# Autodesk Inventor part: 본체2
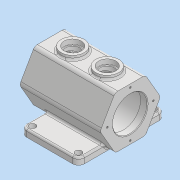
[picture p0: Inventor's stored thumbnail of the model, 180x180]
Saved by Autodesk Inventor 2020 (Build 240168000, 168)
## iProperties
Created: 2021-06
Part Number: 본체2
Material: 일반
Document SubType Name: Modeling
Designer: MIRAE
Density: 1 g/cm^3
Appearance: 기본값
Author: MIRAE
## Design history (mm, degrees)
sketch "스케치1"
  geometry: L1 (50, -75)-(-50, -75); L2 (-50, -75)-(-50, 75); L3 (-50, 75)-(50, 75); L4 (50, 75)-(50, -75); L5 (50, -75)-(-50, 75); L6 (-50, -75)-(50, 75); 1 further point
  constraints: 12 end point, 2 midpoint, 2 parallel, 1 horizontal, 1 perpendicular
  dimensions: "d0" = 100 distance of L2.end L3.end; "d1" = 150 distance of L1.end L2.end
extrude "돌출1" new body sketch "스케치1" distance "d2" = 12; taper "d3" = 0 deg
fillet "모깎기1" dims "d51" = 10
sketch "스케치8"
  geometry: C1 r 5.5 at (-40, 65); A1 r 10 centre (-40, 65) between (-40, 75) and (-50, 65) reference; 1 further point
  constraints: 1 centre point, 1 coincident
  dimensions: "d52" = 11 diameter of C1
extrude "돌출4" cut sketch "스케치8" extent not by distance; stored distance "d53" = 0; taper "d54" = 0 deg
sketch "스케치9"
  geometry: L1 (-50, 65)-(-50, -65) reference; L2 (40, 75)-(-40, 75) reference; 4 further points
  constraints: 1 vertical alignment, 1 other
  dimensions: "d65" = 50 distance from line of L1 point (0, 61) (derived); "d66" = 14 distance from line of point (0, 61) L2
feature "엠보싱1" sketch "스케치9" dims "d0" = 100, "d1" = 150, "d67" = 0.5, "d68" = 0
sketch "스케치10" dims "d72" = 105
  geometry: L1 (0, 50)-(-52.5, 50); L2 (-52.5, 50)-(-26.25, 95.466); L3 (-26.25, 95.466)-(26.25, 95.466); L4 (26.25, 95.466)-(52.5, 50); L5 (52.5, 50)-(26.25, 4.534); L6 (26.25, 4.534)-(-26.25, 4.534); L7 (-26.25, 4.534)-(-52.5, 50); L8 (-65, 0)-(65, 0) reference; 2 further points
  constraints: 14 end point, 1 coincident, 1 horizontal, 1 horizontal alignment, 15 other
  dimensions: "d73" = 50 distance between parallel lines of L8 L1
extrude "돌출5" join sketch "스케치10" distance "d74" = 75; taper "d75" = 0 deg
sketch "스케치11"
  geometry: L1 (-50, 52.5)-(-95.466, 26.25) reference; L2 (-95.466, -26.25)-(-50, -52.5) reference; L3 (-12, 30.561)-(-12, -30.561) reference; L4 (-12, 30.561)-(-50, 52.5) reference; L5 (-50, 52.5)-(-95.466, 26.25) reference; L6 (-95.466, 26.25)-(-95.466, -26.25) reference; L7 (-95.466, -26.25)-(-50, -52.5) reference; L8 (-50, -52.5)-(-12, -30.561) reference; L9 (-50, -52.5)-(-95.466, -26.25); L10 (-95.466, -26.25)-(-95.466, 26.25); L11 (-95.466, 26.25)-(-50, 52.5); L12 (-50, 52.5)-(-4.534, 26.25); L13 (-4.534, 26.25)-(-4.534, -26.25); L14 (-4.534, -26.25)-(-50, -52.5); 8 further points
  constraints: 12 end point, 13 other
extrude "돌출6" join sketch "스케치11" distance "d76" = 65; taper "d77" = 0 deg
sketch "스케치12"
  geometry: L1 (75, 50)-(-65, 50) reference; L2 (75, 50)-(-65, 50); L3 (75, 50)-(63, 50); L4 (63, 50)-(63, 80); L5 (63, 80)-(75, 80); L6 (75, 80)-(75, 50); L7 (63, 50)-(-53, 50); L8 (-53, 50)-(-53, 87.5); L9 (-53, 87.5)-(63, 87.5); L10 (63, 87.5)-(63, 50); L11 (-65, 50)-(-65, 95.466) reference; L12 (-53, 50)-(-65, 50); L13 (-65, 50)-(-65, 80); L14 (-65, 80)-(-53, 80); L15 (-53, 80)-(-53, 50); 3 further points
  constraints: 26 end point, 6 parallel, 4 horizontal, 3 perpendicular, 1 point on line
  dimensions: "d78" = 12 distance of L13.end L14.end; "d79" = 12 distance of L4.end L5.end; "d80" = 60 diameter of L5 L1; "d81" = 75 diameter of L9 L1; "d82" = 60 diameter of L14 L1
revolve "회전2" sketch "스케치12" stored, may be unused: angle "d83" = 90 deg
chamfer "모따기3" distance "d84" = 1; stored, may be unused: second distance "d85" = 2, angle "d86" = 45 deg
node "작업 평면2"
sketch "스케치13"
  geometry: L1 (-75, -26.25)-(-75, 26.25) reference; C1 r 20 at (-35, 0); C2 r 20 at (25, 0); 1 further point
  constraints: 2 centre point, 2 horizontal alignment
  dimensions: "d88" = 40 diameter of C1; "d89" = 40 diameter of C2; "d90" = 40 distance from line of C1.centre L1; "d91" = 60 distance of C2.centre C1.centre
extrude "돌출7" join sketch "스케치13" stored distance "d92" = 65; taper "d93" = 0 deg
sketch "스케치14"
  geometry: C1 r 20 at (0, 0) reference; C2 r 20 at (60, 0) reference; 3 further points
  constraints: 2 coincident
hole "구멍4" sketch "스케치14" at (0, 0), (60, 0) diameter "d94" = 25; stored, may be unused: countersink angle "d98" = 90 deg, drill point angle "d100" = 118 deg; dims "d95" = 8, "d96" = 30, "d97" = 8, "d99" = 10
chamfer "모따기4" distance "d101" = 1; stored, may be unused: second distance "d102" = 2, angle "d103" = 45 deg
sketch "스케치15"
  geometry: C1 r 31 at (-50, 0) reference; 2 further points
  constraints: 1 horizontal alignment
  dimensions: "d104" = 40 distance of C1.centre point (-90, 0)
hole "구멍5" sketch "스케치15" at (-90, 0) diameter "d105" = 3.242; stored, may be unused: countersink angle "d109" = 90 deg, drill point angle "d111" = 118 deg; dims "d106" = 8, "d107" = 30, "d108" = 8, "d110" = 10
sketch "스케치16"
  geometry: L1 (0, 0)-(90, 0); L2 (50, 0)-(95.621, 45.621); C1 r 37.5 at (50, 0) reference; A1 r 40 centre (50, 0) between (90, 0) and (78.284, 28.284)
  constraints: 4 end point, 2 point on circle, 1 centre point, 1 coincident, 1 point on line
  dimensions: "d115" = 80 diameter of A1; "d116" = 45 deg angle of L1 L2
hole "구멍6" sketch "스케치16" at (78.284, 28.284) diameter "d117" = 3.242; stored, may be unused: countersink angle "d121" = 90 deg, drill point angle "d123" = 118 deg; dims "d118" = 8, "d119" = 30, "d120" = 8, "d122" = 10
fillet "모깎기11" dims "d129" = 5
fillet "모깎기13" dims "d131" = 8
fillet "모깎기14" dims "d132" = 3
fillet "모깎기15" dims "d133" = 3
fillet "모깎기17" dims "d135" = 8
fillet "모깎기18" dims "d136" = 3
sketch "스케치17"
  geometry: L1 (-50, 0)-(-118.177, 0); L2 (-118.177, 0)-(-118.177, -65.415); L3 (-118.177, -65.415)-(-50, -65.415); L4 (-50, -65.415)-(-50, 0); C1 r 31 at (-50, 0) reference; C2 r 30 at (-50, 0) reference; 1 further point
  constraints: 8 end point, 2 parallel, 1 horizontal, 1 perpendicular
extrude "돌출8" cut sketch "스케치17" extent not by distance; stored distance "d137" = 0; taper "d138" = 0 deg
node "솔리드1"
mirror "미러1"
mirror "미러2"
pattern_circular "원형 패턴3" dims angle "d113" = 360 deg
pattern_circular "원형 패턴4" dims angle "d125" = 360 deg
node "투영된 루프2"
feature "A9D066F2-1C7D-4E18-AEED-F7BC21143FA4" dims "d94" = 25, "d95" = 8, "d96" = 30, "d97" = 8, "d98" = 90 deg, "d99" = 10, "d100" = 118 deg
other parameters: "d87" = 102.5
